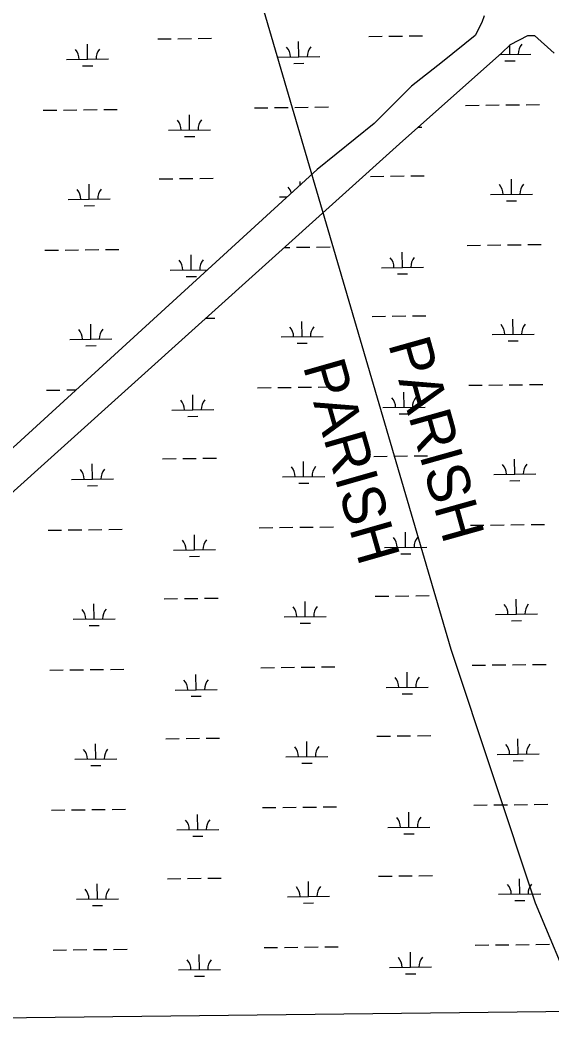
# Model space of a CAD drawing. Extents: x 3684037 to 3722149, y 433263 to 459021.
# Drawn here: x 3690697 to 3691961, y 438677 to 441077 of the extents above; entities that cross this region are included whole.
import ezdxf

# ---------------------------------------------------------------- set-up
doc = ezdxf.new("R2010")
doc.units = 0
for name, color, linetype in [('V-GRID-FRAM', 7, 'Continuous'), ('V-TOPO-BNDY', 7, 'Continuous'), ('V-TOPO-GNAM-IDEN', 7, 'Continuous'), ('V-TOPO-SHOR', 7, 'Continuous'), ('V-WETL-SWMP', 7, 'Continuous')]:
    doc.layers.add(name, color=color, linetype=linetype)

msp = doc.modelspace()

# ---------------------------------------------------------------- linework, layer by layer
at = {"layer": 'V-GRID-FRAM'}
msp.add_lwpolyline([(3688058.9, 456858.9), (3719789.3, 457228.1), (3720008.8, 439046.9), (3688262.6, 438677.5), (3688058.9, 456858.9)], dxfattribs=at)
at = {"layer": 'V-TOPO-BNDY'}
for p, q in [((3691173.9, 441450.6), (3691721.3, 439582.2)), ((3691721.3, 439582.2), (3691921.5, 438979.5)), ((3691921.5, 438979.5), (3692029.2, 438721.3))]:
    msp.add_line(p, q, dxfattribs=at)
at = {"layer": 'V-TOPO-SHOR'}
for p, q in [((3691800, 441087.6), (3691794.8, 441071.9)), ((3691794.8, 441071.9), (3691779.2, 441040.6)), ((3691779.2, 441040.6), (3691700.9, 440978)), ((3691862.6, 441019.7), (3691904.3, 441040.6)), ((3691904.3, 441040.6), (3691920, 441040.6)), ((3691920, 441040.6), (3691966.9, 440998.8)), ((3691841.8, 440998.8), (3691862.6, 441019.7)), ((3691607, 440790.1), (3691841.8, 440998.8)), ((3691700.9, 440978), (3691627.9, 440920.5)), ((3691627.9, 440920.5), (3691539.2, 440831.8)), ((3691539.2, 440831.8), (3691403.6, 440722.2)), ((3690569.1, 439855.9), (3691607, 440790.1)), ((3691403.6, 440722.2), (3690563.9, 439955))]:
    msp.add_line(p, q, dxfattribs=at)
at = {"layer": 'V-WETL-SWMP'}
for p, q in [((3691800, 441087.6), (3691794.8, 441071.9)), ((3691794.8, 441071.9), (3691779.2, 441040.6)), ((3691024.3, 441032.6), (3691056.3, 441033)), ((3691072.3, 441033.2), (3691104.3, 441033.6)), ((3691120.3, 441033.8), (3691152.2, 441034.1)), ((3691526.1, 441038.5), (3691558.1, 441038.9)), ((3691574.1, 441039), (3691606.1, 441039.4)), ((3691622.1, 441039.6), (3691654.1, 441040)), ((3691779.2, 441040.6), (3691700.9, 440978)), ((3691862.6, 441019.7), (3691904.3, 441040.6)), ((3691904.3, 441040.6), (3691920, 441040.6)), ((3691920, 441040.6), (3691966.9, 440998.8)), ((3690857.7, 440984.3), (3690857.3, 441020.3)), ((3691359.6, 440990.1), (3691359.2, 441026.1)), ((3691841.8, 440998.8), (3691862.6, 441019.7)), ((3691861.5, 440995.9), (3691861.2, 441018.3)), ((3690807.7, 440983.7), (3690907.7, 440984.9)), ((3691309.6, 440989.5), (3691409.6, 440990.7)), ((3691607, 440790.1), (3691841.8, 440998.8)), ((3691838.2, 440995.7), (3691911.5, 440996.5)), ((3690845.9, 440968.7), (3690869.9, 440969)), ((3691347.8, 440974.5), (3691371.8, 440974.8)), ((3691700.9, 440978), (3691627.9, 440920.5)), ((3691849.7, 440980.4), (3691873.7, 440980.7)), ((3691627.9, 440920.5), (3691539.2, 440831.8)), ((3690752.3, 440863), (3690784.3, 440863.3)), ((3690800.3, 440863.5), (3690832.3, 440863.9)), ((3690848.3, 440864.1), (3690880.3, 440864.5)), ((3690896.3, 440864.6), (3690928.3, 440865)), ((3691254.2, 440868.8), (3691286.2, 440869.2)), ((3691302.2, 440869.4), (3691334.2, 440869.7)), ((3691350.2, 440869.9), (3691382.2, 440870.3)), ((3691398.2, 440870.5), (3691430.2, 440870.9)), ((3691756.1, 440874.6), (3691788.1, 440875)), ((3691804.1, 440875.2), (3691836, 440875.6)), ((3691852, 440875.8), (3691884, 440876.1)), ((3691900, 440876.3), (3691932, 440876.7)), ((3691100.2, 440816.3), (3691099.8, 440852.3)), ((3691050.2, 440815.7), (3691150.2, 440816.8)), ((3691539.2, 440831.8), (3691403.6, 440722.2)), ((3691643.6, 440822.6), (3691652.1, 440822.7)), ((3690569.1, 439855.9), (3691607, 440790.1)), ((3691088.4, 440800.7), (3691112.4, 440801)), ((3691403.6, 440722.2), (3690563.9, 439955)), ((3691028.1, 440700), (3691060.1, 440700.4)), ((3691076.1, 440700.5), (3691108.1, 440700.9)), ((3691124.1, 440701.1), (3691156.1, 440701.5)), ((3691363.2, 440685.3), (3691363.1, 440693.5)), ((3691530, 440705.8), (3691562, 440706.2)), ((3691578, 440706.4), (3691610, 440706.8)), ((3691626, 440706.9), (3691658, 440707.3)), ((3691865.4, 440663.3), (3691864.9, 440699.3)), ((3690861.6, 440651.6), (3690861.2, 440687.6)), ((3690811.6, 440651), (3690911.6, 440652.2)), ((3691313.5, 440656.9), (3691332.3, 440657.1)), ((3691815.4, 440662.7), (3691915.4, 440663.9)), ((3691853.5, 440647.7), (3691877.5, 440648)), ((3690849.8, 440636), (3690873.8, 440636.3)), ((3690756.2, 440530.3), (3690788.2, 440530.7)), ((3690804.2, 440530.9), (3690836.2, 440531.2)), ((3690852.2, 440531.4), (3690884.2, 440531.8)), ((3690900.2, 440532), (3690932.2, 440532.4)), ((3691325.8, 440536.9), (3691338, 440537.1)), ((3691354, 440537.3), (3691386, 440537.6)), ((3691402, 440537.8), (3691434, 440538.2)), ((3691605.9, 440489.5), (3691605.5, 440525.5)), ((3691759.9, 440542), (3691791.9, 440542.4)), ((3691807.9, 440542.5), (3691839.9, 440542.9)), ((3691855.9, 440543.1), (3691887.9, 440543.5)), ((3691903.9, 440543.7), (3691935.9, 440544)), ((3691104.1, 440483.6), (3691103.6, 440519.6)), ((3691054.1, 440483), (3691142.9, 440484.1)), ((3691555.9, 440488.9), (3691655.9, 440490)), ((3691092.2, 440468), (3691116.2, 440468.3)), ((3691594.1, 440473.9), (3691618.1, 440474.2)), ((3691138.7, 440368.6), (3691160, 440368.8)), ((3691367.4, 440324.8), (3691366.9, 440360.8)), ((3691533.9, 440373.2), (3691565.9, 440373.5)), ((3691581.9, 440373.7), (3691613.9, 440374.1)), ((3691629.9, 440374.3), (3691661.9, 440374.7)), ((3691869.2, 440330.6), (3691868.8, 440366.6)), ((3690865.5, 440319), (3690865.1, 440355)), ((3690815.5, 440318.4), (3690915.5, 440319.5)), ((3691317.4, 440324.2), (3691417.4, 440325.4)), ((3691355.5, 440309.2), (3691379.5, 440309.5)), ((3691819.2, 440330.1), (3691919.2, 440331.2)), ((3691857.4, 440315.1), (3691881.4, 440315.4)), ((3690853.7, 440303.4), (3690877.7, 440303.7)), ((3690760, 440197.7), (3690792, 440198)), ((3690808, 440198.2), (3690830.3, 440198.5)), ((3691261.9, 440203.5), (3691293.9, 440203.9)), ((3691309.9, 440204.1), (3691341.9, 440204.4)), ((3691357.9, 440204.6), (3691389.9, 440205)), ((3691405.9, 440205.2), (3691437.9, 440205.5)), ((3691609.8, 440156.8), (3691609.4, 440192.8)), ((3691763.8, 440209.3), (3691795.8, 440209.7)), ((3691811.8, 440209.9), (3691843.8, 440210.3)), ((3691859.8, 440210.5), (3691891.8, 440210.8)), ((3691907.8, 440211), (3691939.8, 440211.4)), ((3691107.9, 440151), (3691107.5, 440187)), ((3691057.9, 440150.4), (3691157.9, 440151.5)), ((3691559.8, 440156.2), (3691659.8, 440157.4)), ((3691598, 440141.2), (3691622, 440141.5)), ((3691096.1, 440135.4), (3691120.1, 440135.7)), ((3690869.4, 439986.3), (3690868.9, 440022.3)), ((3691035.9, 440034.7), (3691067.9, 440035.1)), ((3691083.9, 440035.2), (3691115.9, 440035.6)), ((3691131.9, 440035.8), (3691163.9, 440036.2)), ((3691371.2, 439992.2), (3691370.8, 440028.1)), ((3691537.7, 440040.5), (3691569.7, 440040.9)), ((3691585.7, 440041.1), (3691617.7, 440041.5)), ((3691633.7, 440041.6), (3691665.7, 440042)), ((3691873.1, 439998), (3691872.7, 440034)), ((3691823.1, 439997.4), (3691923.1, 439998.6)), ((3690819.4, 439985.7), (3690919.4, 439986.9)), ((3691321.2, 439991.6), (3691421.2, 439992.7)), ((3691359.4, 439976.6), (3691383.4, 439976.9)), ((3691861.3, 439982.4), (3691885.3, 439982.7)), ((3690857.5, 439970.7), (3690881.5, 439971)), ((3691815.7, 439877.2), (3691847.7, 439877.6)), ((3691863.7, 439877.8), (3691895.7, 439878.2)), ((3691911.7, 439878.4), (3691943.7, 439878.7)), ((3690763.9, 439865), (3690795.9, 439865.4)), ((3690811.9, 439865.6), (3690843.9, 439865.9)), ((3690859.9, 439866.1), (3690891.9, 439866.5)), ((3690907.9, 439866.7), (3690939.9, 439867.1)), ((3691111.8, 439818.3), (3691111.4, 439854.3)), ((3691265.8, 439870.8), (3691297.8, 439871.2)), ((3691313.8, 439871.4), (3691345.8, 439871.8)), ((3691361.8, 439872), (3691393.8, 439872.3)), ((3691409.8, 439872.5), (3691441.8, 439872.9)), ((3691613.7, 439824.1), (3691613.3, 439860.1)), ((3691767.7, 439876.7), (3691799.7, 439877.1)), ((3691061.8, 439817.7), (3691161.8, 439818.9)), ((3691563.7, 439823.6), (3691663.7, 439824.7)), ((3691601.9, 439808.6), (3691625.9, 439808.9)), ((3691100, 439802.7), (3691124, 439803)), ((3690873.2, 439653.7), (3690872.8, 439689.7)), ((3691039.7, 439702), (3691071.7, 439702.4)), ((3691087.7, 439702.6), (3691119.7, 439703)), ((3691135.7, 439703.1), (3691167.7, 439703.5)), ((3691375.1, 439659.5), (3691374.7, 439695.5)), ((3691541.6, 439707.9), (3691573.6, 439708.2)), ((3691589.6, 439708.4), (3691621.6, 439708.8)), ((3691637.6, 439709), (3691669.6, 439709.4)), ((3691877, 439665.3), (3691876.6, 439701.3)), ((3691827, 439664.8), (3691927, 439665.9)), ((3690823.2, 439653.1), (3690923.2, 439654.2)), ((3690861.4, 439638.1), (3690885.4, 439638.4)), ((3691325.1, 439658.9), (3691425.1, 439660.1)), ((3691363.3, 439643.9), (3691387.3, 439644.2)), ((3691865.2, 439649.8), (3691889.2, 439650)), ((3691771.5, 439544), (3691803.5, 439544.4)), ((3691819.5, 439544.6), (3691851.5, 439545)), ((3691867.5, 439545.2), (3691899.5, 439545.5)), ((3691915.5, 439545.7), (3691947.5, 439546.1)), ((3690767.8, 439532.4), (3690799.8, 439532.7)), ((3690815.8, 439532.9), (3690847.8, 439533.3)), ((3690863.8, 439533.5), (3690895.8, 439533.8)), ((3690911.8, 439534), (3690943.8, 439534.4)), ((3691115.7, 439485.7), (3691115.3, 439521.7)), ((3691269.7, 439538.2), (3691301.7, 439538.6)), ((3691317.7, 439538.8), (3691349.7, 439539.1)), ((3691365.7, 439539.3), (3691397.7, 439539.7)), ((3691413.7, 439539.9), (3691445.7, 439540.2)), ((3691617.5, 439491.5), (3691617.1, 439527.5)), ((3691065.7, 439485.1), (3691165.7, 439486.2)), ((3691103.9, 439470.1), (3691127.9, 439470.4)), ((3691567.5, 439490.9), (3691667.5, 439492.1)), ((3691605.7, 439475.9), (3691629.7, 439476.2)), ((3691545.5, 439375.2), (3691577.5, 439375.6)), ((3691593.5, 439375.8), (3691625.5, 439376.1)), ((3691641.5, 439376.3), (3691673.5, 439376.7)), ((3690877.1, 439321), (3690876.7, 439357)), ((3691043.6, 439369.4), (3691075.6, 439369.7)), ((3691091.6, 439369.9), (3691123.6, 439370.3)), ((3691139.6, 439370.5), (3691171.6, 439370.9)), ((3691379, 439326.8), (3691378.6, 439362.8)), ((3691880.8, 439332.7), (3691880.4, 439368.7)), ((3691329, 439326.3), (3691429, 439327.4)), ((3691830.9, 439332.1), (3691930.8, 439333.3)), ((3690827.1, 439320.4), (3690927.1, 439321.6)), ((3690865.3, 439305.4), (3690889.3, 439305.7)), ((3691367.2, 439311.3), (3691391.2, 439311.6)), ((3691869, 439317.1), (3691893, 439317.4)), ((3691273.5, 439205.5), (3691305.5, 439205.9)), ((3691321.5, 439206.1), (3691353.5, 439206.5)), ((3691369.5, 439206.7), (3691401.5, 439207)), ((3691417.5, 439207.2), (3691449.5, 439207.6)), ((3691775.4, 439211.4), (3691807.4, 439211.8)), ((3691823.4, 439211.9), (3691855.4, 439212.3)), ((3691871.4, 439212.5), (3691903.4, 439212.9)), ((3691919.4, 439213.1), (3691951.4, 439213.4)), ((3690771.7, 439199.7), (3690803.7, 439200.1)), ((3690819.7, 439200.3), (3690851.7, 439200.6)), ((3690867.7, 439200.8), (3690899.7, 439201.2)), ((3690915.7, 439201.4), (3690947.6, 439201.7)), ((3691119.5, 439153), (3691119.1, 439189)), ((3691621.4, 439158.8), (3691621, 439194.8)), ((3691571.4, 439158.3), (3691671.4, 439159.4)), ((3691069.5, 439152.4), (3691169.5, 439153.6)), ((3691107.7, 439137.4), (3691131.7, 439137.7)), ((3691609.6, 439143.3), (3691633.6, 439143.6)), ((3691095.5, 439037.3), (3691127.5, 439037.7)), ((3691143.5, 439037.8), (3691175.5, 439038.2)), ((3691549.4, 439042.6), (3691581.4, 439042.9)), ((3691597.4, 439043.1), (3691629.4, 439043.5)), ((3691645.4, 439043.7), (3691677.3, 439044.1)), ((3690881, 438988.4), (3690880.6, 439024.4)), ((3691047.5, 439036.7), (3691079.5, 439037.1)), ((3691382.8, 438994.2), (3691382.4, 439030.2)), ((3691884.7, 439000), (3691884.3, 439036)), ((3691332.8, 438993.6), (3691432.8, 438994.8)), ((3691834.7, 438999.5), (3691934.7, 439000.6)), ((3690831, 438987.8), (3690931, 438988.9)), ((3690869.2, 438972.8), (3690893.1, 438973.1)), ((3691371, 438978.6), (3691395, 438978.9)), ((3691872.9, 438984.5), (3691896.9, 438984.7)), ((3691277.4, 438872.9), (3691309.4, 438873.3)), ((3691325.4, 438873.4), (3691357.4, 438873.8)), ((3691373.4, 438874), (3691405.4, 438874.4)), ((3691421.4, 438874.6), (3691453.4, 438874.9)), ((3691779.3, 438878.7), (3691811.3, 438879.1)), ((3691827.3, 438879.3), (3691859.3, 438879.7)), ((3691875.3, 438879.8), (3691907.3, 438880.2)), ((3691923.3, 438880.4), (3691955.3, 438880.8)), ((3690775.5, 438867), (3690807.5, 438867.4)), ((3690823.5, 438867.6), (3690855.5, 438868)), ((3690871.5, 438868.2), (3690903.5, 438868.5)), ((3690919.5, 438868.7), (3690951.5, 438869.1)), ((3691123.4, 438820.4), (3691123, 438856.3)), ((3691625.3, 438826.2), (3691624.9, 438862.2)), ((3691575.3, 438825.6), (3691675.3, 438826.8)), ((3691073.4, 438819.8), (3691173.4, 438820.9)), ((3691111.6, 438804.8), (3691135.6, 438805.1)), ((3691613.5, 438810.6), (3691637.5, 438810.9)), ((3695283.3, 438759.2), (3689307.1, 438689.6))]:
    msp.add_line(p, q, dxfattribs=at)
for centre, start, end in [((3690802.5, 440984.1), 359.8949, 41.4385), ((3690913, 440985.4), 139.8949, 181.4385), ((3691304.4, 440989.9), 359.8949, 41.4385), ((3691414.9, 440991.2), 139.8949, 181.4385), ((3691916.7, 440997.1), 139.8949, 181.4385), ((3691806.2, 440995.8), 359.8949, 4.4387), ((3691044.9, 440816.1), 359.8949, 41.4385), ((3691155.4, 440817.4), 139.8949, 181.4385), ((3690806.4, 440651.4), 359.8949, 41.4385), ((3690916.9, 440652.7), 139.8949, 181.4385), ((3691308.2, 440657.3), 14.7088, 41.4385), ((3691810.1, 440663.1), 359.8949, 41.4385), ((3691920.6, 440664.4), 139.8949, 181.4385), ((3691048.8, 440483.4), 359.8949, 41.4385), ((3691159.3, 440484.7), 139.8949, 181.4385), ((3691550.7, 440489.3), 359.8949, 41.4385), ((3691661.2, 440490.6), 139.8949, 181.4385), ((3690810.2, 440318.8), 359.8949, 41.4385), ((3690920.7, 440320.1), 139.8949, 181.4385), ((3691312.1, 440324.6), 359.8949, 41.4385), ((3691422.6, 440325.9), 139.8949, 181.4385), ((3691814, 440330.5), 359.8949, 41.4385), ((3691924.5, 440331.8), 139.8949, 181.4385), ((3691052.7, 440150.8), 359.8949, 41.4385), ((3691163.2, 440152.1), 139.8949, 181.4385), ((3691554.6, 440156.6), 359.8949, 41.4385), ((3691665, 440157.9), 139.8949, 181.4385), ((3691928.3, 439999.1), 139.8949, 181.4385), ((3690814.1, 439986.1), 359.8949, 41.4385), ((3690924.6, 439987.4), 139.8949, 181.4385), ((3691316, 439992), 359.8949, 41.4385), ((3691426.5, 439993.3), 139.8949, 181.4385), ((3691817.9, 439997.8), 359.8949, 41.4385), ((3691056.6, 439818.1), 359.8949, 41.4385), ((3691167, 439819.4), 139.8949, 181.4385), ((3691558.4, 439824), 359.8949, 41.4385), ((3691668.9, 439825.3), 139.8949, 181.4385), ((3691821.7, 439665.2), 359.8949, 41.4385), ((3691932.2, 439666.5), 139.8949, 181.4385), ((3690818, 439653.5), 359.8949, 41.4385), ((3690928.5, 439654.8), 139.8949, 181.4385), ((3691319.9, 439659.3), 359.8949, 41.4385), ((3691430.3, 439660.6), 139.8949, 181.4385), ((3691060.4, 439485.5), 359.8949, 41.4385), ((3691170.9, 439486.8), 139.8949, 181.4385), ((3691562.3, 439491.3), 359.8949, 41.4385), ((3691672.8, 439492.6), 139.8949, 181.4385), ((3691323.7, 439326.7), 359.8949, 41.4385), ((3691434.2, 439328), 139.8949, 181.4385), ((3691825.6, 439332.5), 359.8949, 41.4385), ((3691936.1, 439333.8), 139.8949, 181.4385), ((3690821.9, 439320.8), 359.8949, 41.4385), ((3690932.3, 439322.1), 139.8949, 181.4385), ((3691566.2, 439158.7), 359.8949, 41.4385), ((3691676.7, 439160), 139.8949, 181.4385), ((3691064.3, 439152.8), 359.8949, 41.4385), ((3691174.8, 439154.1), 139.8949, 181.4385), ((3691327.6, 438994), 359.8949, 41.4385), ((3691438.1, 438995.3), 139.8949, 181.4385), ((3691829.5, 438999.9), 359.8949, 41.4385), ((3691940, 439001.2), 139.8949, 181.4385), ((3690825.7, 438988.2), 359.8949, 41.4385), ((3690936.2, 438989.5), 139.8949, 181.4385), ((3691570, 438826), 359.8949, 41.4385), ((3691680.5, 438827.3), 139.8949, 181.4385), ((3691068.2, 438820.2), 359.8949, 41.4385), ((3691178.6, 438821.5), 139.8949, 181.4385)]:
    msp.add_arc(centre, 35.2, start, end, dxfattribs=at)

# ---------------------------------------------------------------- texts
at = {"layer": 'V-TOPO-GNAM-IDEN'}
for rotation, p in [(285.6846, (3691571.7, 440308)), (285.9559, (3691368.9, 440255.1))]:
    msp.add_text('PARISH', height=100, rotation=rotation, dxfattribs=at).set_placement(p)

doc.saveas('drawing.dxf')
